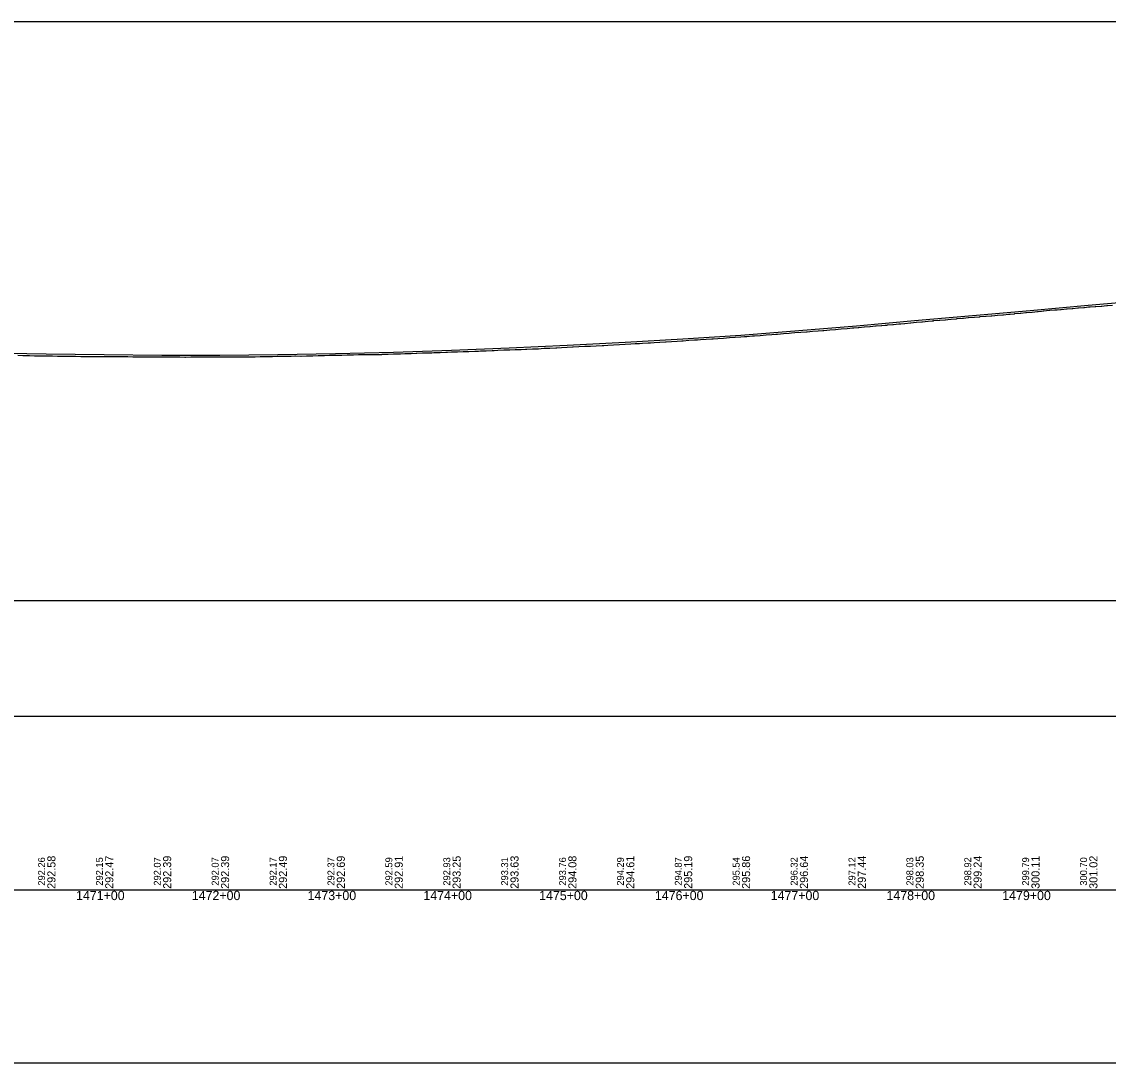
# Model space of a CAD drawing. Extents: x 2898 to 49495, y -15038 to -13538.
# Drawn here: x 36482 to 37421, y -15038 to -14138 of the extents above; entities that cross this region are included whole.
import ezdxf

# ---------------------------------------------------------------- set-up
doc = ezdxf.new("R2010")
doc.units = 0
for name, color, linetype in [('RD_DDB_Profile_EX', 7, 'Continuous'), ('RD_DDB_Profile_PR', 7, 'Continuous'), ('RD_DDB_StaTX', 7, 'Continuous'), ('RD_DDB_StripGrade', 7, 'Continuous'), ('RD_GPK_Profile_Cell', 7, 'Continuous'), ('RD_SHT_ShtClip', 7, 'Continuous')]:
    doc.layers.add(name, color=color, linetype=linetype)

msp = doc.modelspace()

# ---------------------------------------------------------------- linework, layer by layer
at = {"layer": 'RD_DDB_Profile_EX'}
for points in [[(37324.67, -14391.96), (37325.13, -14391.91), (37329.67, -14391.73), (37330.14, -14391.69), (37334.65, -14391.24), (37335.13, -14391.2), (37336.14, -14391.1), (37339.65, -14390.75), (37340.14, -14390.69), (37344.64, -14390.29), (37345.13, -14390.25), (37349.65, -14389.84), (37350.13, -14389.79), (37354.61, -14389.43), (37355.13, -14389.38), (37359.6, -14388.88), (37360.13, -14388.84), (37363.15, -14388.54), (37364.59, -14388.39), (37365.13, -14388.35), (37369.58, -14387.85), (37370.13, -14387.8), (37374.57, -14387.53), (37375.13, -14387.48), (37376.66, -14387.34), (37379.56, -14387.08), (37380.13, -14387.03), (37384.55, -14386.67), (37385.13, -14386.63), (37389.54, -14386.24), (37390.17, -14386.17), (37394.53, -14385.74), (37395.13, -14385.69), (37399.52, -14385.34), (37400.13, -14385.28), (37403.67, -14384.96), (37404.51, -14384.88), (37405.12, -14384.84), (37409.51, -14384.53), (37410.13, -14384.48), (37414.49, -14384.17), (37415.12, -14384.11), (37417.18, -14383.91), (37419.48, -14383.68), (37420.13, -14383.63), (37424.47, -14383.32)], [(37039, -14414.97), (37043.43, -14414.66), (37048.43, -14414.41), (37052.5, -14414.16), (37053.43, -14414.11), (37058.43, -14413.7), (37063.43, -14413.45), (37066.01, -14413.3), (37068.43, -14413.15), (37073.44, -14412.85), (37078.44, -14412.45), (37079.52, -14412.38), (37083.43, -14412.14), (37088.44, -14411.79), (37093.44, -14411.44), (37098.44, -14411.04), (37103.44, -14410.78), (37106.53, -14410.54), (37108.49, -14410.38), (37113.49, -14410.03), (37115.15, -14409.93), (37120.16, -14409.53), (37125.16, -14409.09), (37130.15, -14408.64), (37133.54, -14408.47), (37135.15, -14408.38), (37140.16, -14407.93), (37145.15, -14407.58), (37147.05, -14407.39), (37150.15, -14407.08), (37155.16, -14406.73), (37160.15, -14406.33), (37160.56, -14406.3), (37165.15, -14405.98), (37170.15, -14405.48), (37174.06, -14405.25), (37175.15, -14405.18), (37180.15, -14404.78), (37185.15, -14404.28), (37187.57, -14404.11), (37190.15, -14403.93), (37195.15, -14403.48), (37199.85, -14403.1), (37200.15, -14403.08), (37201.07, -14403.01), (37204.84, -14402.75), (37205.15, -14402.72), (37209.83, -14402.21), (37210.15, -14402.17), (37214.83, -14401.75), (37215.15, -14401.73), (37219.82, -14401.36), (37220.15, -14401.33), (37224.82, -14400.96), (37225.15, -14400.93), (37228.09, -14400.69), (37229.81, -14400.56), (37230.14, -14400.52), (37234.8, -14400.1), (37235.14, -14400.07), (37239.8, -14399.6), (37240.15, -14399.57), (37241.59, -14399.44), (37244.79, -14399.15), (37245.14, -14399.13), (37249.79, -14398.57), (37250.14, -14398.54), (37254.79, -14398.21), (37255.15, -14398.17), (37259.78, -14397.75), (37260.14, -14397.73), (37264.78, -14397.22), (37265.14, -14397.18), (37268.61, -14396.9), (37269.78, -14396.8), (37270.15, -14396.77), (37274.77, -14396.35), (37275.14, -14396.33), (37279.76, -14395.96), (37280.15, -14395.92), (37282.11, -14395.76), (37284.74, -14395.55), (37285.14, -14395.52), (37289.74, -14395.06), (37290.14, -14395.02), (37294.72, -14394.66), (37295.14, -14394.61), (37295.62, -14394.56), (37299.72, -14394.15), (37300.14, -14394.12), (37304.71, -14393.76), (37305.14, -14393.73), (37309.13, -14393.41), (37309.7, -14393.36), (37310.14, -14393.3), (37314.69, -14392.89), (37315.13, -14392.86), (37319.68, -14392.54), (37320.14, -14392.5), (37322.63, -14392.2), (37324.67, -14391.96)], [(36741.85, -14426.83), (36743.22, -14426.83), (36743.72, -14426.83), (36748.23, -14426.69), (36748.72, -14426.68), (36753.23, -14426.64), (36753.72, -14426.62), (36755.36, -14426.58), (36758.23, -14426.52), (36758.71, -14426.52), (36763.24, -14426.38), (36763.71, -14426.36), (36768.25, -14426.32), (36768.87, -14426.3), (36773.25, -14426.16), (36773.7, -14426.15), (36778.24, -14426.15), (36778.68, -14426.15), (36782.37, -14426), (36783.25, -14425.96), (36783.68, -14425.96), (36788.25, -14426), (36788.67, -14425.98), (36793.26, -14425.89), (36793.67, -14425.87), (36795.88, -14425.8), (36798.26, -14425.73), (36798.67, -14425.73), (36803.26, -14425.54), (36803.66, -14425.53), (36808.27, -14425.44), (36808.66, -14425.42), (36809.39, -14425.4), (36813.27, -14425.28), (36813.66, -14425.27), (36818.28, -14425.17), (36818.65, -14425.17), (36822.89, -14424.91), (36823.28, -14424.88), (36823.65, -14424.87), (36828.29, -14424.68), (36828.64, -14424.68), (36833.29, -14424.58), (36833.62, -14424.56), (36836.4, -14424.45), (36838.3, -14424.37), (36838.61, -14424.37), (36843.6, -14424.26), (36848.6, -14423.92), (36849.91, -14423.89), (36853.59, -14423.8), (36858.58, -14423.69), (36863.57, -14423.49), (36868.56, -14423.34), (36873.55, -14423.18), (36876.92, -14423.01), (36878.55, -14422.93), (36883.54, -14422.77), (36888.54, -14422.52), (36890.43, -14422.45), (36893.53, -14422.32), (36898.53, -14422.12), (36903.52, -14421.91), (36903.93, -14421.9), (36908.52, -14421.81), (36913.51, -14421.56), (36917.44, -14421.36), (36918.51, -14421.31), (36923.51, -14421.1), (36928.5, -14421), (36930.94, -14420.83), (36933.5, -14420.65), (36938.5, -14420.4), (36943.49, -14420.15), (36944.45, -14420.12), (36948.49, -14420), (36953.49, -14419.65), (36957.96, -14419.42), (36958.49, -14419.4), (36963.49, -14419.24), (36968.49, -14418.89), (36971.46, -14418.86), (36973.49, -14418.84), (36978.47, -14418.44), (36983.47, -14418.23), (36984.97, -14418.16), (36988.46, -14417.98), (36993.45, -14417.63), (36998.48, -14417.32), (37003.44, -14417.02), (37008.43, -14416.72), (37011.98, -14416.61), (37013.43, -14416.57), (37015.84, -14416.47), (37018.43, -14416.36), (37023.42, -14416.01), (37025.49, -14415.91), (37028.43, -14415.76), (37033.43, -14415.31), (37038.43, -14415.01), (37039, -14414.97)], [(36478.83, -14426.73), (36483.15, -14426.81), (36483.83, -14426.85), (36488.15, -14426.98), (36488.83, -14426.98), (36493.15, -14427.07), (36493.82, -14427.1)], [(36493.82, -14427.1), (36498.15, -14427.1), (36498.82, -14427.09), (36503.16, -14427.18), (36503.82, -14427.2), (36508.16, -14427.2), (36508.82, -14427.2), (36513.16, -14427.32), (36513.81, -14427.32), (36518.16, -14427.5), (36518.81, -14427.53), (36523.17, -14427.53), (36523.81, -14427.53), (36528.17, -14427.58), (36528.81, -14427.59), (36533.17, -14427.8), (36533.8, -14427.8), (36538.16, -14427.67), (36538.79, -14427.68), (36543.17, -14427.72), (36543.79, -14427.71), (36548.17, -14427.76), (36548.79, -14427.76), (36553.17, -14427.72), (36553.79, -14427.74), (36558.17, -14427.74), (36558.79, -14427.73), (36563.17, -14427.78), (36563.79, -14427.78), (36568.17, -14427.87), (36568.79, -14427.87), (36573.17, -14427.87), (36573.79, -14427.88), (36578.17, -14427.97), (36578.79, -14427.96), (36583.17, -14428), (36583.8, -14428.02), (36588.17, -14427.97), (36588.8, -14427.97), (36593.17, -14428.02), (36593.8, -14428.02), (36598.17, -14428.07), (36598.8, -14428.09), (36603.17, -14428.13), (36603.8, -14428.11), (36608.17, -14428.02), (36608.8, -14428.04), (36613.17, -14428.17), (36613.8, -14428.17), (36618.17, -14428.12), (36618.79, -14428.13), (36623.17, -14428.22), (36623.79, -14428.21), (36628.18, -14428.07), (36628.79, -14428.09), (36633.18, -14428.17), (36633.79, -14428.15), (36638.18, -14428.01), (36638.78, -14428.02), (36643.18, -14428.15), (36643.78, -14428.15), (36648.18, -14428.11), (36648.78, -14428.11), (36653.19, -14428.1), (36653.78, -14428.1), (36658.19, -14428.05), (36658.77, -14428.05), (36663.19, -14428.09), (36663.77, -14428.09), (36668.19, -14428.05), (36668.77, -14428.04), (36673.2, -14428), (36673.77, -14428), (36678.2, -14427.96), (36678.76, -14427.95), (36683.19, -14427.94), (36683.75, -14427.94), (36688.2, -14427.81), (36688.75, -14427.81), (36693.2, -14427.76), (36693.75, -14427.74), (36698.2, -14427.69), (36698.74, -14427.69), (36703.21, -14427.6), (36703.74, -14427.6), (36708.21, -14427.5), (36708.73, -14427.5), (36713.21, -14427.5), (36713.73, -14427.48), (36714.84, -14427.43), (36718.21, -14427.3), (36718.73, -14427.29), (36723.22, -14427.33), (36723.73, -14427.32), (36728.35, -14427.18), (36728.72, -14427.18), (36733.22, -14427.13), (36733.72, -14427.12), (36738.22, -14426.85), (36738.72, -14426.83), (36741.85, -14426.83)]]:
    msp.add_lwpolyline(points, dxfattribs=at)
at = {"layer": 'RD_DDB_Profile_PR'}
msp.add_lwpolyline([(36453.38, -14424.48), (36503.38, -14425.58), (36553.38, -14426.13), (36603.38, -14426.52), (36653.38, -14426.5), (36703.38, -14426), (36753.38, -14425.03), (36803.38, -14423.94), (36853.38, -14422.21), (36903.38, -14420.32), (36953.38, -14418.06), (37003.38, -14415.43), (37053.38, -14412.51), (37103.38, -14409.19), (37153.38, -14405.25), (37203.38, -14401.25), (37253.38, -14396.71), (37303.38, -14392.26), (37353.38, -14387.93), (37403.38, -14383.39), (37453.38, -14379.05)], dxfattribs=at)
at = {"layer": 'RD_GPK_Profile_Cell'}
msp.add_line((2976.05, -14888.47), (48721.13, -14888.47), dxfattribs=at)
at = {"layer": 'RD_SHT_ShtClip'}
for points in [[(35975.38, -14138.47), (35975.38, -14638.47), (37475.38, -14638.47), (37475.38, -14638.47), (37475.38, -14138.47), (37475.38, -14138.47)], [(35955.38, -14738.47), (37495.38, -14738.47), (37495.38, -15038.47), (35955.38, -15038.47)]]:
    msp.add_lwpolyline(points, close=True, dxfattribs=at)

# ---------------------------------------------------------------- texts
at = {"layer": 'RD_DDB_StaTX'}
for s, p in [('1471+00', (36529.18, -14897.47)), ('1472+00', (36629.18, -14897.47)), ('1473+00', (36729.18, -14897.47)), ('1474+00', (36829.18, -14897.47)), ('1475+00', (36929.18, -14897.47)), ('1476+00', (37029.18, -14897.47)), ('1477+00', (37129.18, -14897.47)), ('1478+00', (37229.18, -14897.47)), ('1479+00', (37329.18, -14897.47))]:
    msp.add_text(s, height=8, dxfattribs=at).set_placement(p)
at = {"layer": 'RD_DDB_StripGrade'}
for s, height, p in [('292.26', 6, (36502.38, -14884.98)), ('292.58', 7, (36511.38, -14887.72)), ('292.15', 6, (36552.38, -14884.98)), ('292.47', 7, (36561.38, -14887.72)), ('292.07', 6, (36602.38, -14884.98)), ('292.39', 7, (36611.38, -14887.72)), ('292.07', 6, (36652.38, -14884.98)), ('292.39', 7, (36661.38, -14887.72)), ('292.17', 6, (36702.38, -14884.98)), ('292.49', 7, (36711.38, -14887.72)), ('292.37', 6, (36752.38, -14884.98)), ('292.69', 7, (36761.38, -14887.72)), ('292.59', 6, (36802.38, -14884.98)), ('292.91', 7, (36811.38, -14887.72)), ('292.93', 6, (36852.38, -14884.98)), ('293.25', 7, (36861.38, -14887.72)), ('293.31', 6, (36902.38, -14884.98)), ('293.63', 7, (36911.38, -14887.72)), ('293.76', 6, (36952.38, -14884.98)), ('294.08', 7, (36961.38, -14887.72)), ('294.29', 6, (37002.38, -14884.98)), ('294.61', 7, (37011.38, -14887.72)), ('294.87', 6, (37052.38, -14884.98)), ('295.19', 7, (37061.38, -14887.72)), ('295.54', 6, (37102.38, -14884.98)), ('295.86', 7, (37111.38, -14887.72)), ('296.32', 6, (37152.38, -14884.98)), ('296.64', 7, (37161.38, -14887.72)), ('297.12', 6, (37202.38, -14884.98)), ('297.44', 7, (37211.38, -14887.72)), ('298.03', 6, (37252.38, -14884.98)), ('298.35', 7, (37261.38, -14887.72)), ('298.92', 6, (37302.38, -14884.98)), ('299.24', 7, (37311.38, -14887.72)), ('299.79', 6, (37352.38, -14884.98)), ('300.11', 7, (37361.38, -14887.72)), ('300.70', 6, (37402.38, -14884.98)), ('301.02', 7, (37411.38, -14887.72))]:
    msp.add_text(s, height=height, rotation=90, dxfattribs=at).set_placement(p)

doc.saveas('drawing.dxf')
